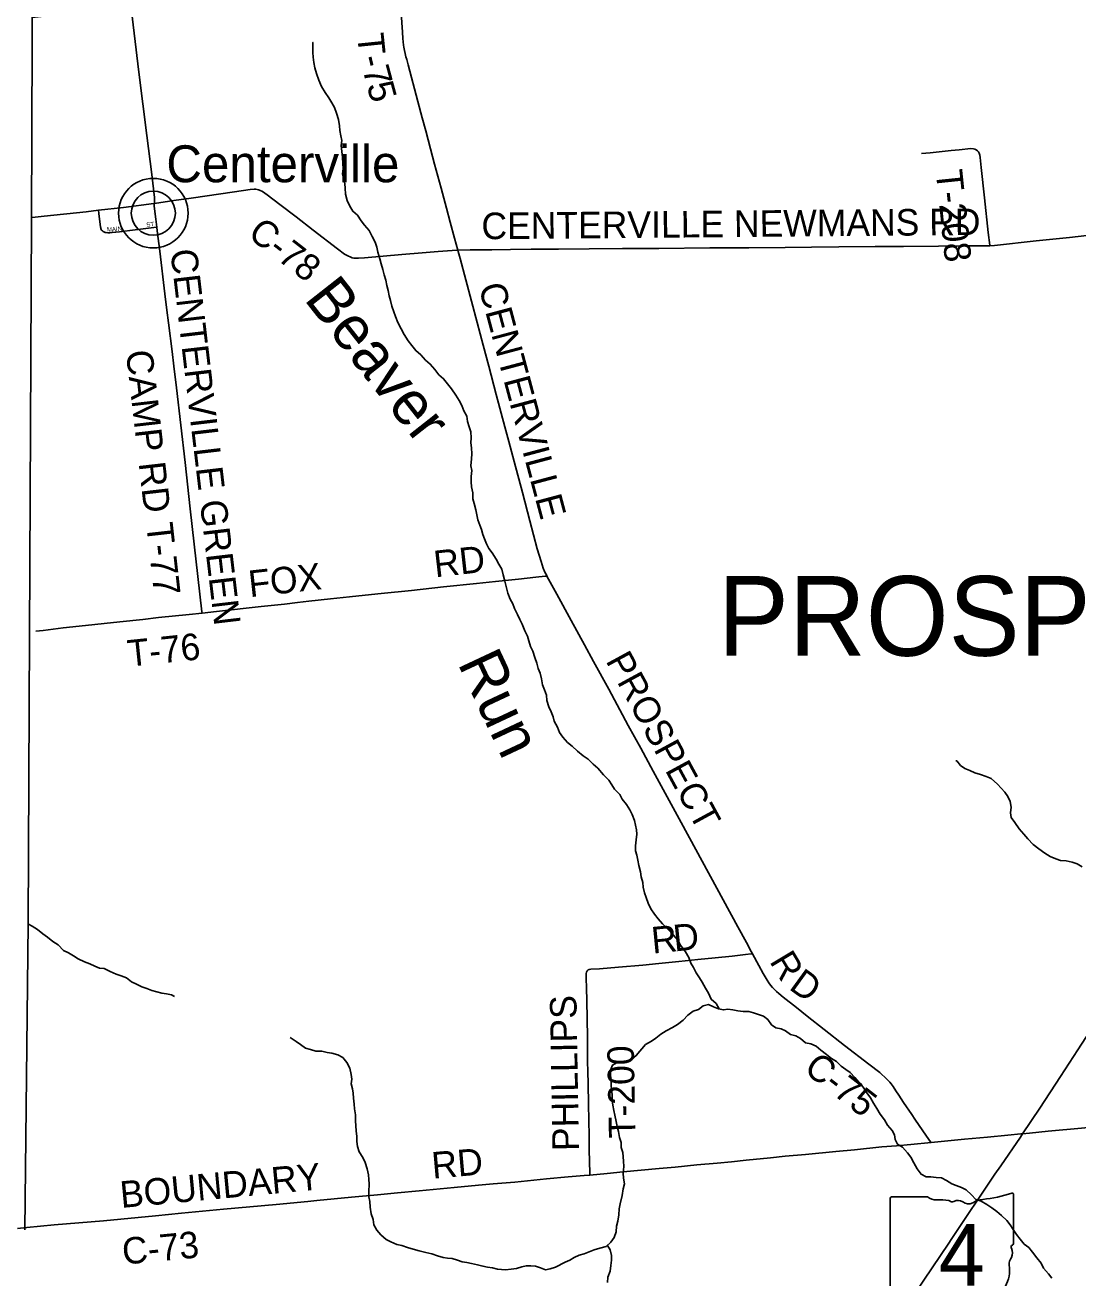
# Model space of a CAD drawing. Extents: x 1584893 to 1934202, y 663575 to 1091909.
# Drawn here: x 1760284 to 1772181, y 897514 to 911667 of the extents above; entities that cross this region are included whole.
import ezdxf

# ---------------------------------------------------------------- set-up
doc = ezdxf.new("R2010")
doc.units = 0
for name, color, linetype in [('GM_X_Adjacent_County', 7, 'Continuous'), ('GM_X_County', 7, 'Continuous'), ('GM_X_County_Road', 7, 'Continuous'), ('GM_X_County_Road_Text', 7, 'Continuous'), ('GM_X_Minor_River', 7, 'Continuous'), ('GM_X_Minor_River_Text', 7, 'Continuous'), ('GM_X_State_Location', 7, 'Continuous'), ('GM_X_State_Route', 7, 'Continuous'), ('GM_X_State_Shield', 7, 'Continuous'), ('GM_X_Township', 7, 'Continuous'), ('GM_X_Township_Road', 7, 'Continuous'), ('GM_X_Township_Road_Text', 7, 'Continuous'), ('GM_X_Township_Subdivision', 7, 'Continuous'), ('GM_X_Township_Subdivision_Text', 7, 'Continuous'), ('GM_X_Township_Text', 7, 'Continuous'), ('GM_X_Unincorporated', 7, 'Continuous'), ('GM_X_Unincorporated_Location', 7, 'Continuous'), ('GM_X_Unincorporated_Text', 7, 'Continuous')]:
    doc.layers.add(name, color=color, linetype=linetype)

msp = doc.modelspace()

# ---------------------------------------------------------------- linework, layer by layer
at = {"layer": 'GM_X_Adjacent_County'}
msp.add_lwpolyline([(1759934, 914025), (1760358, 914021), (1760364, 911751), (1760364, 911476), (1760357, 909471), (1760334, 904783), (1760318, 901515), (1760281, 898058)], dxfattribs=at)
at = {"layer": 'GM_X_County'}
msp.add_lwpolyline([(1760281, 898058), (1760318, 901515), (1760334, 904783), (1760357, 909471), (1760364, 911476), (1760364, 911751), (1760358, 914021), (1759934, 914025)], dxfattribs=at)
at = {"layer": 'GM_X_County_Road'}
for points in [[(1761745, 909651), (1761966, 909685), (1762161, 909713), (1762649, 909783), (1762827, 909808), (1762874, 909812), (1762891, 909812), (1762906, 909811), (1762921, 909807), (1762934, 909802), (1762967, 909785), (1763021, 909749), (1763163, 909638), (1763346, 909499), (1763541, 909348), (1763815, 909139), (1763895, 909080), (1763938, 909056), (1763957, 909048), (1763979, 909039), (1763999, 909035), (1764030, 909033), (1764052, 909033), (1764118, 909037), (1764331, 909055), (1764543, 909074), (1764772, 909094), (1764952, 909110), (1765164, 909124), (1765174, 909124)], [(1761114, 909574), (1761397, 909606), (1761739, 909650), (1761745, 909651)], [(1760364, 909493), (1760500, 909507), (1760973, 909557), (1761114, 909574)], [(1771185, 909174), (1771237, 909177), (1771710, 909228), (1772086, 909268), (1772445, 909307), (1772624, 909326), (1772885, 909355), (1772918, 909359), (1772983, 909366), (1773260, 909397), (1773538, 909426), (1773880, 909462), (1774354, 909512), (1774794, 909559), (1774881, 909570), (1774946, 909580), (1774959, 909582)], [(1765174, 909124), (1765312, 909128), (1765558, 909129), (1765771, 909132), (1766001, 909134), (1766313, 909137), (1766660, 909140), (1767036, 909142), (1767445, 909144), (1768020, 909149), (1768163, 909149), (1768463, 909152), (1768873, 909154), (1769169, 909159), (1769481, 909161), (1769891, 909164), (1770210, 909165), (1770604, 909168), (1770903, 909172), (1771139, 909172), (1771185, 909174)], [(1766181, 905443), (1766179, 905447), (1766159, 905485), (1766140, 905530), (1766114, 905606), (1766092, 905679), (1766072, 905750), (1765989, 906068), (1765904, 906388), (1765810, 906737), (1765750, 906962), (1765705, 907129), (1765608, 907494), (1765523, 907815), (1765462, 908050), (1765393, 908307), (1765199, 909031), (1765179, 909107), (1765174, 909124)], [(1768503, 901176), (1768490, 901200), (1768435, 901302), (1768339, 901480), (1767697, 902660), (1767382, 903237), (1767242, 903497), (1767100, 903756), (1766879, 904165), (1766709, 904477), (1766607, 904664), (1766455, 904939), (1766292, 905239), (1766181, 905443)], [(1770522, 899043), (1770515, 899053), (1770469, 899117), (1770340, 899306), (1770303, 899361), (1770211, 899495), (1770157, 899578), (1770123, 899629), (1770092, 899676), (1770069, 899706), (1770054, 899724), (1770021, 899760), (1770002, 899779), (1769961, 899816), (1769941, 899833), (1769817, 899929), (1769542, 900141), (1769312, 900320), (1769121, 900472), (1769001, 900567), (1768851, 900686), (1768802, 900727), (1768776, 900749), (1768750, 900774), (1768729, 900796), (1768707, 900821), (1768687, 900847), (1768668, 900876), (1768624, 900952), (1768574, 901044), (1768503, 901176)], [(1771556, 899142), (1771633, 899148), (1771846, 899170), (1772221, 899207), (1772564, 899241), (1772678, 899253), (1772776, 899261), (1772924, 899274), (1773267, 899307), (1773463, 899325), (1773806, 899358), (1774133, 899388), (1774329, 899408), (1774786, 899450), (1775113, 899480), (1775260, 899496), (1775439, 899515), (1775554, 899526), (1775635, 899534), (1775700, 899540), (1775733, 899539), (1775748, 899538), (1775764, 899535), (1775826, 899519)], [(1766664, 898675), (1766863, 898694), (1767043, 898711), (1767451, 898749), (1767631, 898766), (1767876, 898790), (1768105, 898811), (1768268, 898827), (1768432, 898844), (1768709, 898872), (1768872, 898888), (1769101, 898908), (1769444, 898942), (1769657, 898962), (1769967, 898993), (1770130, 899007), (1770294, 899021), (1770522, 899043)], [(1770522, 899043), (1770637, 899055), (1770898, 899080), (1771160, 899104), (1771388, 899127), (1771535, 899141), (1771556, 899142)], [(1760199, 898071), (1760303, 898082), (1760614, 898112), (1761169, 898159), (1761562, 898198), (1761758, 898217), (1762052, 898245), (1762527, 898290), (1763122, 898345), (1763481, 898378), (1763579, 898387), (1763971, 898425), (1764265, 898453), (1764494, 898476), (1764739, 898497), (1765131, 898535), (1765409, 898561), (1765572, 898575), (1765817, 898597), (1766177, 898633), (1766422, 898654), (1766602, 898669), (1766664, 898675)]]:
    msp.add_lwpolyline(points, dxfattribs=at)
at = {"layer": 'GM_X_Minor_River'}
for points in [[(1765327, 906451), (1765323, 906505), (1765324, 906567), (1765333, 906633), (1765320, 906688), (1765329, 906766), (1765332, 906824), (1765327, 906890), (1765322, 906948), (1765323, 907004), (1765320, 907070), (1765302, 907129), (1765285, 907189), (1765274, 907249), (1765243, 907308), (1765220, 907370), (1765189, 907427), (1765152, 907486), (1765103, 907559), (1765058, 907615), (1765013, 907672), (1764958, 907717), (1764916, 907776), (1764863, 907837), (1764810, 907880), (1764755, 907941), (1764698, 907990), (1764655, 908046), (1764614, 908101), (1764569, 908172), (1764534, 908237), (1764497, 908305), (1764468, 908374), (1764451, 908426), (1764428, 908491), (1764415, 908555), (1764399, 908609), (1764386, 908670), (1764373, 908724), (1764360, 908786), (1764343, 908845), (1764328, 908905), (1764309, 908969), (1764294, 909026), (1764271, 909100), (1764258, 909156), (1764240, 909213), (1764207, 909278), (1764171, 909346), (1764119, 909405), (1764082, 909456), (1764041, 909518), (1763986, 909563), (1763955, 909622), (1763924, 909685), (1763903, 909757), (1763900, 909823), (1763897, 909873), (1763885, 909928), (1763872, 909988), (1763879, 910042), (1763874, 910102), (1763869, 910174), (1763864, 910239), (1763857, 910307), (1763862, 910361), (1763853, 910417), (1763841, 910475), (1763836, 910528), (1763827, 910600), (1763804, 910672), (1763779, 910737), (1763752, 910789), (1763717, 910846), (1763674, 910905), (1763633, 910972), (1763604, 911046), (1763577, 911119), (1763560, 911183), (1763547, 911245), (1763538, 911304), (1763537, 911356), (1763534, 911418), (1763536, 911470), (1763538, 911470)], [(1768128, 900552), (1768093, 900612), (1768038, 900661), (1768005, 900731), (1767974, 900788), (1767937, 900853), (1767904, 900903), (1767867, 900960), (1767839, 901021), (1767806, 901071), (1767785, 901134), (1767748, 901196), (1767691, 901271), (1767662, 901328), (1767607, 901389), (1767544, 901456), (1767487, 901513), (1767438, 901570), (1767395, 901624), (1767356, 901685), (1767325, 901748), (1767302, 901810), (1767285, 901863), (1767268, 901927), (1767264, 901979), (1767247, 902045), (1767240, 902102), (1767221, 902172), (1767210, 902232), (1767195, 902289), (1767182, 902339), (1767181, 902395), (1767191, 902463), (1767198, 902525), (1767193, 902577), (1767182, 902630), (1767169, 902682), (1767144, 902748), (1767119, 902803), (1767079, 902862), (1767032, 902922), (1767003, 902975), (1766946, 903034), (1766915, 903084), (1766880, 903137), (1766819, 903198), (1766758, 903271), (1766705, 903318), (1766646, 903375), (1766590, 903410), (1766527, 903463), (1766466, 903520), (1766413, 903563), (1766360, 903624), (1766323, 903675), (1766301, 903737), (1766262, 903802), (1766251, 903854), (1766228, 903910), (1766203, 903965), (1766180, 904035), (1766175, 904098), (1766154, 904156), (1766131, 904213), (1766118, 904283), (1766103, 904345), (1766083, 904398), (1766068, 904458), (1766043, 904524), (1766020, 904595), (1765995, 904647), (1765976, 904712), (1765961, 904762), (1765930, 904823), (1765903, 904899), (1765874, 904950), (1765847, 905008), (1765814, 905077), (1765797, 905127), (1765765, 905182), (1765740, 905248), (1765721, 905323), (1765704, 905383), (1765687, 905456), (1765670, 905522), (1765637, 905575), (1765608, 905633), (1765561, 905704), (1765526, 905755), (1765497, 905807), (1765474, 905862), (1765455, 905912), (1765443, 905968), (1765422, 906019), (1765399, 906077), (1765390, 906133), (1765379, 906190), (1765358, 906262), (1765345, 906313), (1765344, 906383), (1765327, 906451)], [(1771199, 903156), (1771143, 903177), (1771080, 903200), (1771018, 903221), (1770961, 903246), (1770905, 903269), (1770854, 903304), (1770812, 903356), (1770802, 903356)], [(1772229, 902159), (1772173, 902190), (1772116, 902210), (1772050, 902224), (1771984, 902229), (1771930, 902247), (1771869, 902274), (1771808, 902311), (1771738, 902362), (1771675, 902410), (1771616, 902473), (1771569, 902527), (1771516, 902588), (1771467, 902657), (1771428, 902716), (1771421, 902768), (1771426, 902832), (1771417, 902894), (1771389, 902951), (1771356, 903003), (1771274, 903093), (1771199, 903156)], [(1760321, 901509), (1760365, 901488), (1760424, 901449), (1760485, 901402), (1760537, 901365), (1760598, 901314), (1760659, 901275), (1760718, 901214), (1760774, 901187), (1760831, 901154), (1760883, 901118), (1760956, 901086), (1761014, 901061), (1761071, 901037), (1761125, 901014), (1761177, 901009), (1761246, 900974), (1761315, 900947), (1761369, 900928), (1761431, 900905), (1761488, 900858), (1761543, 900833), (1761603, 900804), (1761658, 900783), (1761718, 900762), (1761772, 900747), (1761829, 900729), (1761883, 900722), (1761937, 900711), (1761973, 900694)], [(1769277, 900087), (1769222, 900132), (1769163, 900159), (1769103, 900170), (1769046, 900219), (1768992, 900250), (1768933, 900265), (1768877, 900305), (1768826, 900326), (1768768, 900339), (1768717, 900374), (1768679, 900433), (1768628, 900470), (1768573, 900490), (1768515, 900507), (1768461, 900522), (1768399, 900525), (1768339, 900530), (1768282, 900541), (1768226, 900550), (1768176, 900542), (1768118, 900553), (1768065, 900576), (1768007, 900603), (1767945, 900586), (1767894, 900545), (1767832, 900528), (1767772, 900482), (1767721, 900425), (1767656, 900378), (1767600, 900341), (1767528, 900304), (1767467, 900267), (1767413, 900223), (1767362, 900188), (1767296, 900149), (1767190, 900026), (1767136, 899983), (1767081, 899960), (1767029, 899957), (1766973, 899947), (1766921, 899918), (1766898, 899860), (1766899, 899800), (1766905, 899746), (1766906, 899692), (1766911, 899642), (1766918, 899584), (1766919, 899517), (1766926, 899465), (1766938, 899407), (1766947, 899351), (1766964, 899280), (1766973, 899224), (1766990, 899168), (1767001, 899099), (1767018, 899045), (1767021, 898987), (1767040, 898932), (1767042, 898882), (1767047, 898832), (1767050, 898774), (1767043, 898698), (1767048, 898640), (1767057, 898577), (1767041, 898522), (1767033, 898444), (1767010, 898350), (1766999, 898296), (1766992, 898226), (1766981, 898154), (1766967, 898098), (1766962, 898034), (1766939, 897972), (1766902, 897917), (1766849, 897867), (1766777, 897850), (1766715, 897833), (1766659, 897810), (1766601, 897785), (1766546, 897770), (1766488, 897744), (1766438, 897715), (1766388, 897690), (1766279, 897635), (1766217, 897618), (1766163, 897605), (1766109, 897628), (1766053, 897645), (1766000, 897652), (1765948, 897652), (1765896, 897639), (1765837, 897620), (1765775, 897611), (1765712, 897606), (1765622, 897611), (1765564, 897626), (1765510, 897635), (1765457, 897648), (1765397, 897661), (1765329, 897678)], [(1765329, 897678), (1765277, 897687), (1765224, 897697), (1765170, 897714), (1765110, 897733), (1765058, 897736), (1765007, 897745), (1764943, 897762), (1764882, 897785), (1764814, 897800), (1764736, 897819), (1764669, 897840), (1764605, 897859), (1764541, 897880), (1764484, 897891), (1764418, 897922), (1764365, 897947), (1764304, 898002), (1764258, 898055), (1764225, 898115), (1764216, 898172), (1764193, 898236), (1764184, 898312), (1764179, 898378), (1764170, 898431), (1764167, 898487), (1764172, 898575), (1764169, 898625), (1764164, 898679), (1764149, 898748), (1764126, 898816), (1764101, 898875), (1764058, 898939), (1764041, 898998), (1764031, 899054), (1764034, 899112), (1764027, 899174), (1764022, 899231), (1764019, 899287), (1764016, 899357), (1764005, 899423), (1764002, 899475), (1763995, 899546), (1763993, 899600), (1763984, 899650), (1763969, 899706), (1763976, 899760), (1763970, 899810), (1763954, 899885), (1763921, 899949), (1763873, 900002), (1763820, 900035), (1763750, 900054), (1763697, 900061), (1763637, 900074), (1763571, 900075), (1763511, 900094), (1763454, 900109), (1763398, 900150), (1763347, 900183), (1763292, 900221), (1763280, 900228)], [(1771886, 897511), (1771847, 897561), (1771794, 897624), (1771764, 897681), (1771715, 897742), (1771668, 897803), (1771625, 897859), (1771574, 897894), (1771527, 897953), (1771488, 898004), (1771450, 898060), (1771415, 898113), (1771376, 898164), (1771319, 898219), (1771266, 898266), (1771210, 898304), (1771151, 898345), (1771086, 898380), (1771026, 898399), (1770977, 898454), (1770920, 898509), (1770866, 898536), (1770807, 898559), (1770755, 898576), (1770696, 898615), (1770638, 898646), (1770580, 898647), (1770519, 898656), (1770465, 898654), (1770409, 898685), (1770364, 898746), (1770327, 898813), (1770294, 898877), (1770257, 898928), (1770198, 898991), (1770143, 899026), (1770115, 899078), (1770108, 899129), (1770081, 899181), (1770028, 899240), (1769995, 899299), (1769948, 899363), (1769907, 899428), (1769870, 899487), (1769837, 899550), (1769796, 899604), (1769753, 899669), (1769706, 899726), (1769662, 899777), (1769609, 899834), (1769558, 899870), (1769506, 899905), (1769453, 899960), (1769396, 899991), (1769339, 900038), (1769277, 900087)], [(1766864, 897881), (1766897, 897830), (1766912, 897766), (1766911, 897716), (1766904, 897654), (1766897, 897590), (1766870, 897524), (1766867, 897462)]]:
    msp.add_lwpolyline(points, dxfattribs=at)
at = {"layer": 'GM_X_State_Route'}
for points in [[(1771309, 898780), (1771531, 899105), (1771556, 899142), (1771749, 899433), (1771984, 899789), (1772181, 900091), (1772370, 900379), (1772577, 900695), (1772722, 900914), (1772884, 901160), (1773207, 901655), (1773487, 902080), (1773855, 902642), (1774234, 903218), (1774449, 903547), (1774630, 903821), (1774909, 904247), (1775007, 904397), (1775030, 904428)], [(1770750, 897948), (1771244, 898685), (1771309, 898780)], [(1767638, 893291), (1767792, 893524), (1767924, 893723), (1768306, 894296), (1768843, 895101), (1769144, 895551), (1769472, 896042), (1769837, 896587), (1770121, 897009), (1770440, 897487), (1770724, 897908), (1770750, 897948)]]:
    msp.add_lwpolyline(points, dxfattribs=at)
at = {"layer": 'GM_X_State_Shield'}
for p, q in [((1771453, 897902), (1771453, 898455)), ((1770061, 898410), (1770061, 897354)), ((1770482, 898429), (1770074, 898429)), ((1771453, 897902), (1771453, 897902))]:
    msp.add_line(p, q, dxfattribs=at)
for centre, radius, start, end in [((1770957, 899869), 1476, 275.8445, 288.9065), ((1771437, 898457), 15.5, 351.8621, 97.738), ((1770077, 898413), 16.1, 98.1301, 188.1301), ((1770579, 898551), 156, 231.6195, 271.1119), ((1770631, 897835), 562, 80.4867, 94.9883), ((1770759, 898418), 45.1, 219.7921, 297.1024), ((1770825, 898296), 93.8, 54.4667, 119.1411), ((1770946, 898464), 113, 233.8562, 294.8282), ((1771145, 898106), 297, 97.3462, 120.7689), ((1771449, 897861), 24, 107.944, 210.337), ((1771436, 897900), 16.6, 289.6038, 7.7341), ((1771508, 897671), 105, 136.8065, 186.9296), ((1771297, 897792), 144, 340.033, 23.6496), ((1771040, 897600), 369, 292.3089, 8.9858)]:
    msp.add_arc(centre, radius, start, end, dxfattribs=at)
at = {"layer": 'GM_X_Township'}
msp.add_lwpolyline([(1760281, 898058), (1760318, 901515), (1760334, 904783), (1760357, 909471), (1760364, 911476), (1760364, 911751), (1761469, 911878), (1764527, 912231), (1773348, 913292)], dxfattribs=at)
at = {"layer": 'GM_X_Township_Road'}
for points in [[(1765174, 909124), (1765138, 909261), (1765089, 909442), (1765047, 909598), (1764985, 909825), (1764912, 910097), (1764866, 910269), (1764812, 910470), (1764772, 910620), (1764723, 910803), (1764613, 911216), (1764596, 911277), (1764588, 911309), (1764579, 911346), (1764572, 911381), (1764565, 911416), (1764561, 911441), (1764553, 911514), (1764547, 911585), (1764530, 911860), (1764525, 911946), (1764499, 912291)], [(1761745, 909651), (1761745, 909653), (1761747, 909670), (1761748, 909687), (1761745, 909720), (1761715, 909980), (1761660, 910420), (1761570, 911136), (1761475, 911920)], [(1770750, 910248), (1770512, 910222), (1770414, 910214)], [(1771185, 909174), (1771185, 909182), (1771168, 909322), (1771125, 909714), (1771088, 910057), (1771077, 910171), (1771072, 910198), (1771064, 910219), (1771056, 910233), (1771046, 910246), (1771033, 910256), (1771018, 910263), (1771003, 910268), (1770970, 910271), (1770839, 910258), (1770750, 910248)], [(1761773, 909385), (1761761, 909475), (1761743, 909621), (1761743, 909637), (1761745, 909651)], [(1762284, 905025), (1762283, 905040), (1762151, 906202), (1762092, 906724), (1762044, 907147), (1761994, 907569), (1761966, 907814), (1761946, 907979), (1761906, 908304), (1761887, 908447), (1761864, 908629), (1761806, 909114), (1761778, 909343), (1761773, 909385)], [(1762284, 905025), (1762447, 905043), (1762953, 905100), (1763214, 905126), (1763361, 905144), (1763492, 905158), (1763736, 905185), (1763949, 905208), (1764128, 905227), (1764308, 905245), (1764651, 905281), (1765011, 905319), (1765386, 905359), (1765599, 905381), (1765860, 905407), (1766056, 905430), (1766161, 905441), (1766181, 905443)], [(1760404, 904819), (1760487, 904829), (1760716, 904856), (1760895, 904876), (1761353, 904925), (1761614, 904953), (1761793, 904973), (1762137, 905008), (1762284, 905025)], [(1766647, 899715), (1766643, 899837), (1766641, 899968), (1766638, 900214), (1766636, 900460), (1766629, 900804), (1766626, 900886), (1766624, 900935), (1766625, 900952), (1766627, 900968), (1766634, 900982), (1766646, 900993), (1766660, 900999), (1766677, 901001), (1766775, 901006), (1766988, 901023), (1767265, 901047), (1767445, 901066), (1767673, 901089), (1767885, 901110), (1768081, 901130), (1768276, 901150), (1768423, 901167), (1768490, 901175), (1768503, 901176)], [(1766664, 898675), (1766664, 898706), (1766661, 898821), (1766659, 898968), (1766657, 899132), (1766655, 899280), (1766651, 899493), (1766647, 899690), (1766647, 899715)]]:
    msp.add_lwpolyline(points, dxfattribs=at)
at = {"layer": 'GM_X_Township_Subdivision'}
for points in [[(1761157, 909341), (1761149, 909351), (1761145, 909359), (1761141, 909368), (1761139, 909376), (1761137, 909385), (1761118, 909538), (1761114, 909574)], [(1761157, 909341), (1761167, 909334), (1761173, 909330), (1761180, 909328), (1761189, 909325), (1761202, 909323), (1761221, 909321), (1761243, 909321), (1761269, 909322), (1761350, 909330), (1761528, 909355), (1761738, 909381), (1761773, 909385)]]:
    msp.add_lwpolyline(points, dxfattribs=at)
at = {"layer": 'GM_X_Unincorporated'}
for radius in [393, 249]:
    msp.add_circle((1761733, 909542), radius, dxfattribs=at)
at = {"layer": 'GM_X_Unincorporated_Location'}
msp.add_line((1761733, 909542), (1761733, 909542), dxfattribs=at)

# ---------------------------------------------------------------- texts
at = {"layer": 'GM_X_County_Road_Text'}
for s, rotation, p in [('CENTERVILLE NEWMANS RD', 0.4961, (1765442, 909247)), ('C-78', 322.3037, (1762787, 909280)), ('CENTERVILLE', 284.9376, (1765407, 908714)), ('PROSPECT', 298.5021, (1766840, 904486)), ('R', 300.947, (1768690, 901090)), ('D', 324.0736, (1768904, 900783)), ('C-75', 322.0345, (1769070, 899850)), ('RD', 4.9698, (1764891, 898634)), ('BOUNDARY', 5.3257, (1761371, 898304)), ('C-73', 5.5032, (1761395, 897663))]:
    msp.add_text(s, height=300, rotation=rotation, dxfattribs=at).set_placement(p)
at = {"layer": 'GM_X_Minor_River_Text'}
for s, rotation, p in [('Beaver', 308.1436, (1763427, 908571)), ('Run', 295.1279, (1765167, 904460))]:
    msp.add_text(s, height=500, rotation=rotation, dxfattribs=at).set_placement(p)
at = {"layer": 'GM_X_State_Location'}
msp.add_text('4', height=1, rotation=0, dxfattribs=at).set_placement((1770591, 897739))
for s in ['s', 'r']:
    msp.add_text(s, height=1, dxfattribs=at).set_placement((1770741, 897812))
at = {"layer": 'GM_X_State_Shield'}
msp.add_text('4', height=696, dxfattribs=at).set_placement((1770609, 897428))
at = {"layer": 'GM_X_Township_Road_Text'}
for s, rotation, p in [('T', 275.9204, (1764035, 911561)), ('7', 284.9979, (1764095, 911168)), ('-', 283.2469, (1764065, 911297)), ('5', 285.1599, (1764143, 910988)), ('T-208', 275.9094, (1770574, 910019)), ('CENTERVILLE GREEN', 276.6981, (1761925, 909122)), ('CAMP RD', 276.5417, (1761422, 907981)), ('T-77', 276.3785, (1761652, 906031)), ('RD', 6.4491, (1764919, 905427)), ('FOX', 6.4149, (1762825, 905203)), ('T-76', 5.9186, (1761456, 904418)), ('R', 5.5607, (1767376, 901177)), ('D', 5.8441, (1767623, 901201)), ('PHILLIPS', 90.9495, (1766543, 898949)), ('T-200', 91.1183, (1767182, 899095))]:
    msp.add_text(s, height=300, rotation=rotation, dxfattribs=at).set_placement(p)
at = {"layer": 'GM_X_Township_Subdivision_Text'}
for s, rotation, p in [('M', 356.4282, (1761206, 909336)), ('A', 5.5402, (1761267, 909333)), ('I', 6.7096, (1761312, 909337)), ('N', 6.8585, (1761334, 909340)), ('ST', 7.1217, (1761657, 909385))]:
    msp.add_text(s, height=50, rotation=rotation, dxfattribs=at).set_placement(p)
at = {"layer": 'GM_X_Township_Text'}
msp.add_text('PROSPECT', height=900, rotation=0, dxfattribs=at).set_placement((1768112, 904542))
at = {"layer": 'GM_X_Unincorporated_Text'}
msp.add_text('Centerville', height=417, rotation=0, dxfattribs=at).set_placement((1761880, 909891))

doc.saveas('drawing.dxf')
